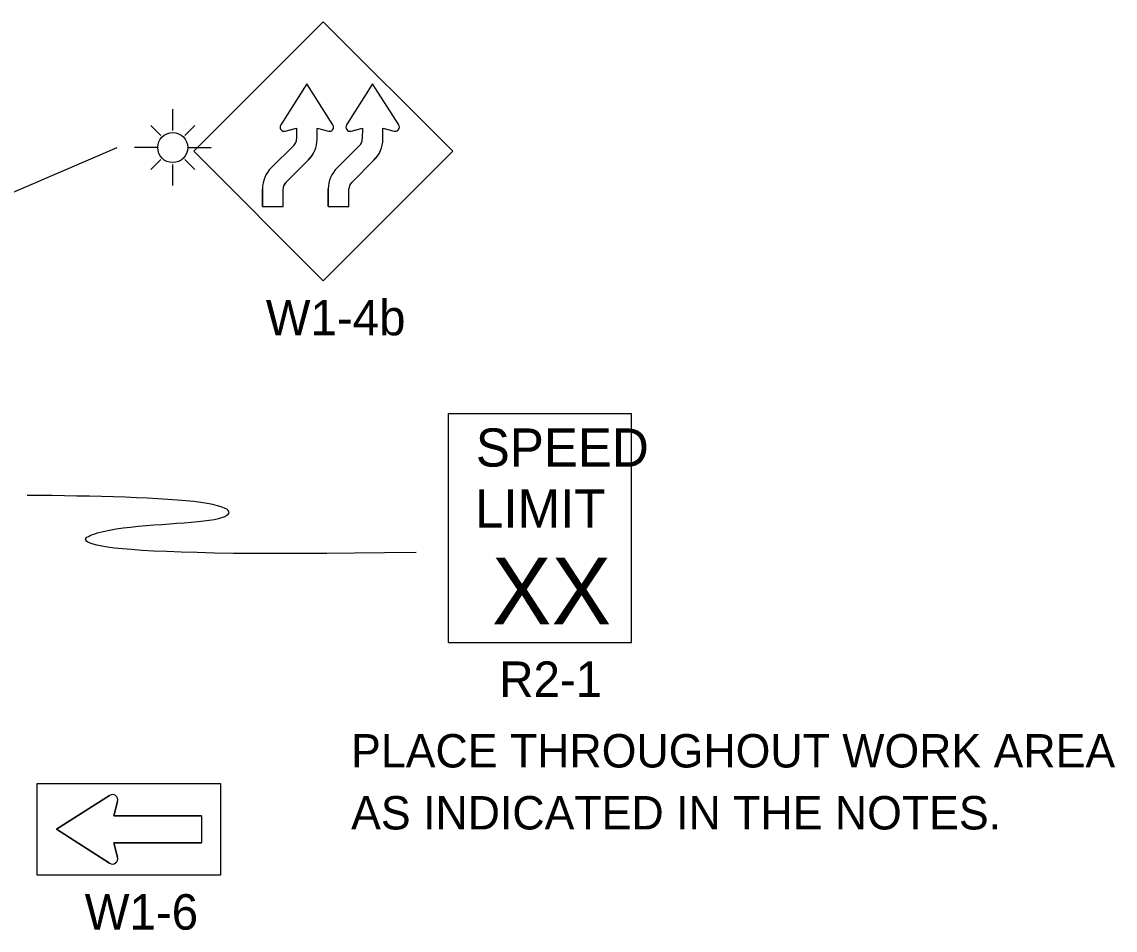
# Model space of a CAD drawing. Extents: x 16577 to 18475, y 5712 to 6919.
# Drawn here: x 17150.1 to 17379.3, y 6459.8 to 6650.3 of the extents above; entities that cross this region are included whole.
import ezdxf

# ---------------------------------------------------------------- set-up
doc = ezdxf.new("R2010")
doc.units = 0
doc.layers.add('TRAFFIC_SIGNS_PR', color=7, linetype='Continuous')
doc.layers.add('TYPICAL_TEXT_DIMEN_PR', color=7, linetype='Continuous')

msp = doc.modelspace()

# ---------------------------------------------------------------- linework, layer by layer
at = {"layer": 'TRAFFIC_SIGNS_PR'}
for p, q in [((17213.26, 6650.28), (17186.11, 6623.13)), ((17240.41, 6623.13), (17213.26, 6650.28)), ((17181.72, 6627.46), (17181.72, 6631.97)), ((17179.21, 6626.42), (17177.1, 6628.53)), ((17184.23, 6626.42), (17186.34, 6628.53)), ((17178.57, 6623.91), (17173.73, 6623.91)), ((17184.87, 6623.91), (17189.76, 6623.91)), ((17202.39, 6619.66), (17207.11, 6624.37)), ((17207.11, 6624.37), (17202.39, 6619.66)), ((17216.19, 6619.66), (17220.9, 6624.37)), ((17220.9, 6624.37), (17216.19, 6619.66)), ((17179.21, 6621.4), (17177.1, 6619.29)), ((17184.23, 6621.4), (17186.34, 6619.29)), ((17186.11, 6623.13), (17213.26, 6595.97)), ((17205.45, 6616.61), (17210.16, 6621.32)), ((17205.45, 6616.61), (17210.16, 6621.32)), ((17213.26, 6595.97), (17240.41, 6623.13)), ((17219.24, 6616.61), (17223.96, 6621.32)), ((17219.24, 6616.61), (17223.96, 6621.32)), ((17181.72, 6615.94), (17181.72, 6620.36)), ((17200.53, 6611.54), (17200.53, 6615.24)), ((17204.84, 6611.54), (17204.84, 6615.24)), ((17214.32, 6611.54), (17214.32, 6615.24)), ((17218.64, 6611.54), (17218.64, 6615.24)), ((17200.53, 6611.54), (17204.84, 6611.54)), ((17214.32, 6611.54), (17218.64, 6611.54)), ((17239.5, 6568.13), (17277.9, 6568.13)), ((17239.5, 6520.13), (17239.5, 6568.13)), ((17277.9, 6520.13), (17277.9, 6568.13)), ((17239.5, 6520.13), (17277.9, 6520.13)), ((17168.49, 6488.02), (17157.33, 6480.92)), ((17169.34, 6483.72), (17170.17, 6486.78)), ((17187.73, 6483.72), (17169.34, 6483.72)), ((17187.73, 6483.72), (17187.73, 6478.12)), ((17157.33, 6480.92), (17168.49, 6473.82)), ((17170.17, 6475.06), (17169.34, 6478.12)), ((17169.34, 6478.12), (17187.73, 6478.12))]:
    msp.add_line(p, q, dxfattribs=at)
for points in [[(17215.31, 6628.65), (17209.83, 6637.26), (17204.35, 6628.65)], [(17215.31, 6628.65), (17209.83, 6637.26), (17204.35, 6628.65)], [(17229.11, 6628.65), (17223.63, 6637.26), (17218.15, 6628.65)], [(17229.11, 6628.65), (17223.63, 6637.26), (17218.15, 6628.65)], [(17205.31, 6627.35), (17207.67, 6628), (17207.67, 6625.71)], [(17205.31, 6627.35), (17206.15, 6627.58), (17207.67, 6628), (17207.67, 6625.71)], [(17211.98, 6625.63), (17211.99, 6628), (17214.35, 6627.35)], [(17211.98, 6625.63), (17211.99, 6628), (17214.35, 6627.35)], [(17219.11, 6627.35), (17221.47, 6628), (17221.46, 6625.71)], [(17219.11, 6627.35), (17219.94, 6627.58), (17221.47, 6628), (17221.46, 6625.71)], [(17225.78, 6625.63), (17225.78, 6628), (17228.15, 6627.35)], [(17225.78, 6625.63), (17225.78, 6628), (17228.15, 6627.35)], [(17200.53, 6615.24), (17200.53, 6611.54), (17204.84, 6611.54), (17204.84, 6615.24)], [(17214.32, 6615.24), (17214.32, 6611.54), (17218.64, 6611.54), (17218.64, 6615.24)], [(17168.49, 6473.82), (17157.33, 6480.92), (17168.49, 6488.02)], [(17170.17, 6486.78), (17169.34, 6483.72), (17187.73, 6483.72), (17187.73, 6478.12), (17169.34, 6478.12), (17170.17, 6475.06)]]:
    msp.add_lwpolyline(points, dxfattribs=at)
msp.add_lwpolyline([(17191.73, 6471.32), (17153.33, 6471.32), (17153.33, 6490.52), (17191.73, 6490.52)], close=True, dxfattribs=at)
msp.add_circle((17181.72, 6623.91), 3.15, dxfattribs=at)
for centre, radius, start, end in [((17205.08, 6628.19), 0.866, 147.5288, 285.3852), ((17205.08, 6628.19), 0.864, 147.5204, 285.3986), ((17214.58, 6628.19), 0.866, 254.6828, 32.2708), ((17214.58, 6628.19), 0.866, 254.6799, 32.2804), ((17224.42, 6634.45), 10.8, 212.4569, 212.4665), ((17218.88, 6628.19), 0.864, 147.5204, 285.3986), ((17218.88, 6628.19), 0.866, 147.5288, 285.3852), ((17228.38, 6628.19), 0.866, 254.6828, 32.2708), ((17228.38, 6628.19), 0.866, 254.6799, 32.2804), ((17238.22, 6634.45), 10.8, 212.4569, 212.4665), ((17211.5, 6616.93), 10.8, 74.68, 74.6808), ((17225.3, 6616.93), 10.8, 74.68, 74.6808), ((17205.82, 6625.7), 1.85, 314.2123, 0.1238), ((17205.82, 6625.7), 1.85, 314.2125, 0), ((17205.82, 6625.7), 6.17, 314.2125, 359.3819), ((17205.82, 6625.7), 6.17, 314.7687, 359.3755), ((17219.61, 6625.7), 1.85, 314.2123, 0.1238), ((17219.61, 6625.7), 1.85, 314.2125, 0), ((17219.61, 6625.7), 6.17, 314.2125, 359.3819), ((17219.61, 6625.7), 6.17, 314.7687, 359.3755), ((17206.69, 6615.24), 6.17, 134.2125, 180), ((17206.69, 6615.24), 6.17, 134.2125, 180), ((17206.69, 6615.24), 6.17, 134.2117, 180), ((17220.49, 6615.24), 6.17, 134.2125, 180), ((17220.49, 6615.24), 6.17, 134.2125, 180), ((17220.49, 6615.24), 6.17, 134.2117, 180), ((17206.69, 6615.24), 1.85, 132.372, 180), ((17206.69, 6615.24), 1.85, 134.2125, 180), ((17220.49, 6615.24), 1.85, 132.372, 180), ((17220.49, 6615.24), 1.85, 134.2125, 180), ((17169.09, 6487.08), 1.12, 344.6731, 122.4696), ((17169.09, 6487.08), 1.12, 344.6731, 122.4696), ((17169.09, 6474.76), 1.12, 237.5304, 15.3269), ((17169.09, 6474.76), 1.12, 237.5304, 15.3269)]:
    msp.add_arc(centre, radius, start, end, dxfattribs=at)
at = {"layer": 'TYPICAL_TEXT_DIMEN_PR'}
msp.add_line((17170.01, 6623.87), (17124.64, 6604.3), dxfattribs=at)
msp.add_open_spline([(17232.77, 6538.99), (17159.28, 6537.77), (17160.42, 6544.88), (17195.18, 6544.88), (17195.18, 6550.17), (17164.99, 6550.85), (17151.2, 6550.96)], degree=3, dxfattribs=at)

# ---------------------------------------------------------------- texts
at = {"layer": 'TRAFFIC_SIGNS_PR'}
for s, height, p in [('W1-4b', 7.44, (17201.22, 6584.53)), ('SPEED', 8, (17245.26, 6557)), ('LIMIT', 8, (17245.1, 6544.2)), ('XX', 14.031, (17248.61, 6523.89)), ('R2-1', 7.44, (17250.17, 6508.69)), ('PLACE THROUGHOUT WORK AREA', 7, (17219.11, 6493.89)), ('AS INDICATED IN THE NOTES.', 7, (17219.11, 6480.89)), ('W1-6', 7.44, (17163.27, 6459.88))]:
    msp.add_text(s, height=height, dxfattribs=at).set_placement(p)

doc.saveas('drawing.dxf')
